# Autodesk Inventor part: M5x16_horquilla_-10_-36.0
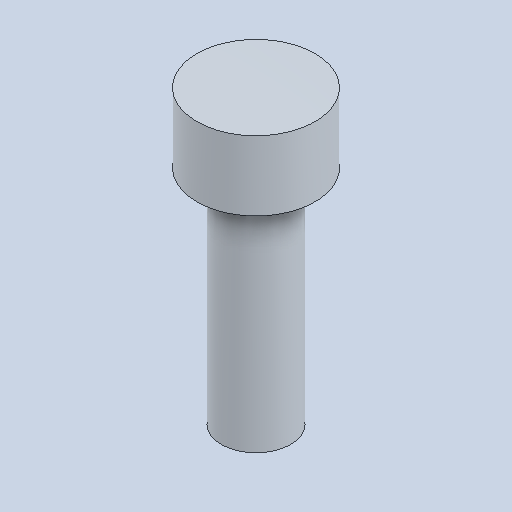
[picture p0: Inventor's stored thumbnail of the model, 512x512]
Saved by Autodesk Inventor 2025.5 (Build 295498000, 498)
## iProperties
Created: 2026-10
Part Number: M5x16_horquilla_-10_-36.0
Material: Genérico
Document SubType Name: Modeling
Designer: Luis M
Density: 1 g/cm^3
Appearance: Valor por defecto
Author: Luis M
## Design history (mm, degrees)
feature "Base1"
node "Sólido1"
